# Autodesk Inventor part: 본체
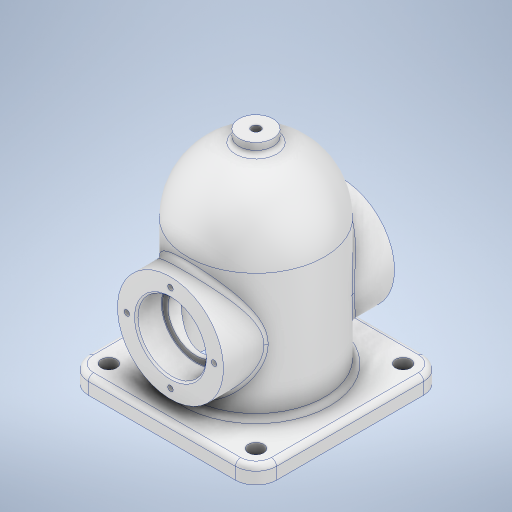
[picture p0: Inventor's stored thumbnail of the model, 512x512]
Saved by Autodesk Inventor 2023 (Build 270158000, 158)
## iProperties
Created: 2025-04
Part Number: 본체
Material: 알루미늄 6061
Document SubType Name: Modeling
Designer: User
Density: 2.7 g/cm^3
Appearance: 알루미늄 - 평지
Mass: 865.907 g
Surface Area: 800.754 cm^2
Volume: 320.706 cm^3
Author: User
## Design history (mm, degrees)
sketch "스케치1"
  geometry: C1 r 31 at (0, 0); 1 further point
  constraints: 1 centre point, 1 coincident
  dimensions: "d0" = 62 diameter of C1
extrude "돌출1" new body sketch "스케치1" stored distance "d1" = 100; taper "d2" = 0 deg
sketch "스케치9"
  geometry: C1 r 10 at (0, 0); 1 further point
  constraints: 1 centre point, 1 coincident
  dimensions: "d32" = 20 diameter of C1
extrude "돌출5" join sketch "스케치9" distance "d33" = 81; taper "d34" = 0 deg
sketch "스케치2"
  geometry: L1 (0, 0)-(0, -48); L2 (0, -48)-(40, -48); L3 (40, -48)-(40, 36); L4 (40, 36)-(0, 36); L5 (0, 36)-(0, 0); L6 (0, 76)-(0, 36); L7 (0, -74.457)-(0, 110.741) reference; C1 r 31 at (0, 0) reference; A1 r 40 centre (0, 36) between (40, 36) and (0, 76); 3 further points
  constraints: 12 end point, 4 perpendicular, 2 point on circle, 1 centre point, 1 coincident, 1 collinear, 1 point on line, 1 vertical
  dimensions: "d3" = 48 distance of L1.start L1.end; "d4" = 40 distance of L1.end L2.end; "d5" = 84 distance of L2.end L3.end
revolve "회전1" sketch "스케치2" stored, may be unused: angle "d6" = 90 deg
sketch "스케치7"
  geometry: L1 (-55, 55)-(55, 55); L2 (55, 55)-(55, -55); L3 (55, -55)-(-55, -55); L4 (-55, -55)-(-55, 55); L5 (-55, 55)-(55, -55); L6 (55, 55)-(-55, -55); 1 further point
  constraints: 12 end point, 2 midpoint, 2 parallel, 1 horizontal, 1 perpendicular
  dimensions: "d28" = 110 distance of L2.end L3.end; "d29" = 110 distance of L1.end L2.end
extrude "돌출4" join sketch "스케치7" distance "d30" = 10; taper "d31" = 0 deg
sketch "스케치3"
  geometry: L1 (40, -48)-(40, 36) reference; L2 (-40, -48)-(-40, 36) reference; L3 (32, -48)-(32, 36); L4 (-32, -48)-(-32, 36); L5 (40, -48)-(-40, -48) reference; L6 (0, -72.8)-(0, 100.8) reference; L7 (0, 68)-(0, -48); L8 (0, -48)-(32, -48); A1 r 40 centre (0, 36) between (40, 36) and (-40, 36) reference; A2 r 32 centre (0, 36) between (32, 36) and (-32, 36); 2 further points
  constraints: 8 end point, 3 point on circle, 3 point on line, 2 parallel, 1 centre point, 1 collinear, 1 midpoint
  dimensions: "d7" = 8 radial gap between concentric circles of A1 A2; "d8" = 8 distance between parallel lines of L1 L3; "d9" = 8 distance between parallel lines of L2 L4
revolve "회전2" sketch "스케치3" stored, may be unused: angle "d10" = 90 deg
sketch "스케치4"
  geometry: C1 r 20 at (0, 0); 1 further point
  constraints: 1 centre point, 1 coincident
  dimensions: "d11" = 40 diameter of C1
extrude "돌출2" cut sketch "스케치4" distance "d12" = 15; taper "d13" = 0 deg
sketch "스케치5"
  geometry: C1 r 16.5 at (0, 0); 1 further point
  constraints: 1 centre point, 1 coincident
  dimensions: "d14" = 33 diameter of C1
extrude "돌출3" cut sketch "스케치5" extent not by distance; stored distance "d15" = 0; taper "d16" = 0 deg
sketch "스케치6" dims "d17" = 51
  geometry: 3 further points
  constraints: 1 coincident, 1 horizontal alignment, 2 other
hole "구멍1" sketch "스케치6" at (-25.5, 0) diameter "d18" = 3.242; stored, may be unused: countersink angle "d22" = 90 deg, drill point angle "d24" = 118 deg; dims "d19" = 8, "d20" = 4, "d21" = 2, "d23" = 10
sketch "스케치8"
  geometry: 1 further point
sketch "스케치10"
  geometry: 2 further points
  constraints: 1 coincident
hole "구멍2" sketch "스케치10" at (0, 0) diameter "d35" = 5.1881; stored, may be unused: countersink angle "d39" = 90 deg, drill point angle "d41" = 118 deg; dims "d36" = 20, "d37" = 4, "d38" = 2, "d40" = 16
sketch "스케치11"
  geometry: L1 (-43, 43)-(43, 43); L2 (43, 43)-(43, -43); L3 (43, -43)-(-43, -43); L4 (-43, -43)-(-43, 43); L5 (-43, 43)-(43, -43); L6 (43, 43)-(-43, -43); C1 r 2.594 at (0, 0) reference; C2 r 4.5 at (-43, 43); C3 r 4.5 at (43, 43); C4 r 4.5 at (-43, -43); C5 r 4.5 at (43, -43); 1 further point
  constraints: 12 end point, 4 centre point, 4 coincident, 2 midpoint, 2 parallel, 1 horizontal, 1 perpendicular
  dimensions: "d42" = 86 distance of L2.end L3.end; "d43" = 86 distance of L1.end L2.end; "d44" = 9 diameter of C2; "d45" = 9 diameter of C3; "d46" = 9 diameter of C4; "d47" = 9 diameter of C5
extrude "돌출6" cut sketch "스케치11" extent not by distance; stored distance "d48" = 0; taper "d49" = 0 deg
node "작업 평면1"
sketch "스케치14"
  geometry: L1 (48, 55)-(48, -55) reference; L2 (73.8, 0)-(-106.8, 0) reference; 2 further points
  constraints: 1 point on line, 1 other
  dimensions: "d51" = 30 distance from line of L1 point (18, 0)
feature "엠보싱1" sketch "스케치14" dims "d52" = 0.5, "d53" = 0
fillet "모깎기1" dims "d54" = 12
fillet "모깎기2" dims "d55" = 0.3
chamfer "모따기1" distance "d56" = 1; stored, may be unused: second distance "d57" = 2, angle "d58" = 45 deg
fillet "모깎기3" dims "d59" = 3
sketch "스케치15"
  geometry: 1 further point
sketch "스케치16"
  geometry: 1 further point
feature "̘耀̚耀̜耀̞耀̠耀̢耀̤耀̦耀" dims "d0" = 62, "d1" = 100, "d2" = 0, "d3" = 48, "d4" = 40, "d5" = 84, "d6" = 90 deg, "d7" = 8, "d8" = 8, "d9" = 8, "d10" = 90 deg, "d11" = 40, "d12" = 15, "d13" = 0, "d14" = 33, "d15" = 0, "d16" = 0, "d17" = 51, "d18" = 3.242, "d19" = 8, "d20" = 4, "d21" = 2, "d22" = 90 deg, "d23" = 10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
node "솔리드1"
pattern_circular "원형 패턴1" dims angle "d26" = 360 deg
mirror "미러1"
feature "A9D066F2-1C7D-4E18-AEED-F7BC21143FA4" dims "d18" = 3.242, "d19" = 8, "d20" = 4, "d21" = 2, "d22" = 90 deg, "d23" = 10, "d24" = 118 deg
